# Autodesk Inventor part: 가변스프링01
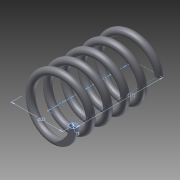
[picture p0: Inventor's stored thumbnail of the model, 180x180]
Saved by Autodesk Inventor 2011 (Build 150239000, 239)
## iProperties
Created: 2015-05
Part Number: 가변스프링01
Material: 탄소강
Document SubType Name: Modeling
Designer: Administrator
Mass: 18.8475 g
Surface Area: 32.4803 cm^2
Volume: 2.39485 cm^3
Density: 7.87 g/cm^3
Author: Administrator
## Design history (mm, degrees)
sketch "스케치1"
  geometry: L1 (0, 0)-(11, 0); L2 (11, 0)-(11, 25.358); L3 (11, 25.358)-(0, 25.358); L4 (0, 25.358)-(0, 0); C1 r 1.5 at (11, 0); 1 further point
  constraints: 8 end point, 2 coincident, 2 parallel, 1 centre point, 1 horizontal, 1 perpendicular
  dimensions: "d0" = 25.35829 distance of L1.end L2.end (derived); "d1" = 22 diameter of L2 L4; "d2" = 3 diameter of C1
feature "코일1" sketch "스케치1" pitch "d3" = 10; turns "d5" = 5; dims "d4" = 25.35829 (= d0), "d6" = 0, angle "d7" = 90 deg, angle "d8" = 90 deg, "d9" = 0, "d10" = 0
sketch "스케치2"
  geometry: L1 (-12.5, 0)-(-9.5, 0) reference; 1 further point
  constraints: 1 horizontal alignment
extrude "돌출1" cut sketch "스케치2" stored distance "d11" = 10; taper "d12" = 0 deg
node "작업 평면1"
sketch "스케치3"
  geometry: L1 (1.5, 0)-(-1.5, 0) reference; 1 further point
  constraints: 1 horizontal alignment
extrude "돌출2" cut sketch "스케치3" stored distance "d13" = 10; taper "d14" = 0 deg
node "솔리드1"
node "절단 모서리 투영1"
node "절단 모서리 투영2"
